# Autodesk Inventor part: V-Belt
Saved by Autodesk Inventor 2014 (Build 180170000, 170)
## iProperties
Created: 2013-12
Part Number: V-Belt
Material: Rubber
Document SubType Name: Modeling
Designer: Bram
Density: 0.93 g/cm^3
Appearance: Rubber - Black - Version 1.1
CustomPartVersion: 1
Author: Bram
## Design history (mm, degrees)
sketch "Sketch Path" dims "d1" = 10.6172 (= da_Bw)
  geometry: L1 (-1.588, -546.177)-(-7.515, -0.082); L2 (7.514, 0.129)-(16.921, -545.917); A1 r 7.515 centre (0, 0) between (7.514, 0.129) and (-7.515, -0.082); A2 r 9.255 centre (7.667, -546.076) between (-1.588, -546.177) and (16.921, -545.917)
  constraints: 4 end point, 4 point on circle, 2 centre point
node "Cross Section Plane"
workaxis "Work Axis1"
workaxis "Work Axis2"
sketch "Cross Section"
  geometry: L1 (0, 2.682)-(0, -5.255); L2 (-5.309, 0)-(5.309, 0); L3 (-3.396, -5.255)-(3.396, -5.255); L4 (3.396, -5.255)-(6.285, 2.682); L5 (6.285, 2.682)-(-6.285, 2.682); L6 (-6.285, 2.682)-(-3.396, -5.255); 2 further points
  constraints: 12 end point, 3 midpoint, 2 parallel, 2 point on line, 1 coincident, 1 perpendicular, 1 vertical, 1 other
  dimensions: "d1" = 10.6172 distance of L2.start L2.end (= da_Bw); "d2" = 7.9375 distance between parallel lines of L3 L5 (= da_H); "d3" = 2.6822 distance between parallel lines of L5 L2 (= da_Hw); "d5" = 40 deg angle of L4 L6 (= da_Alfa)
feature "Belt" sketch "Cross Section" dims "d6" = 0
body "Solid1"
other parameters: "d0" = 0, "da_Alfa" = 40 deg [user parameter; used in 1 equation term], "da_H" = 7.9375 [user parameter; used in 1 equation term], "da_Bw" = 10.6172 [user parameter; used in 1 equation term], "da_Hw" = 2.6822 [user parameter; used in 1 equation term], "d7" = 0, "d8" = 0, "d9" = 0
